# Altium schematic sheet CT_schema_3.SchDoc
size 298 x 247 mm
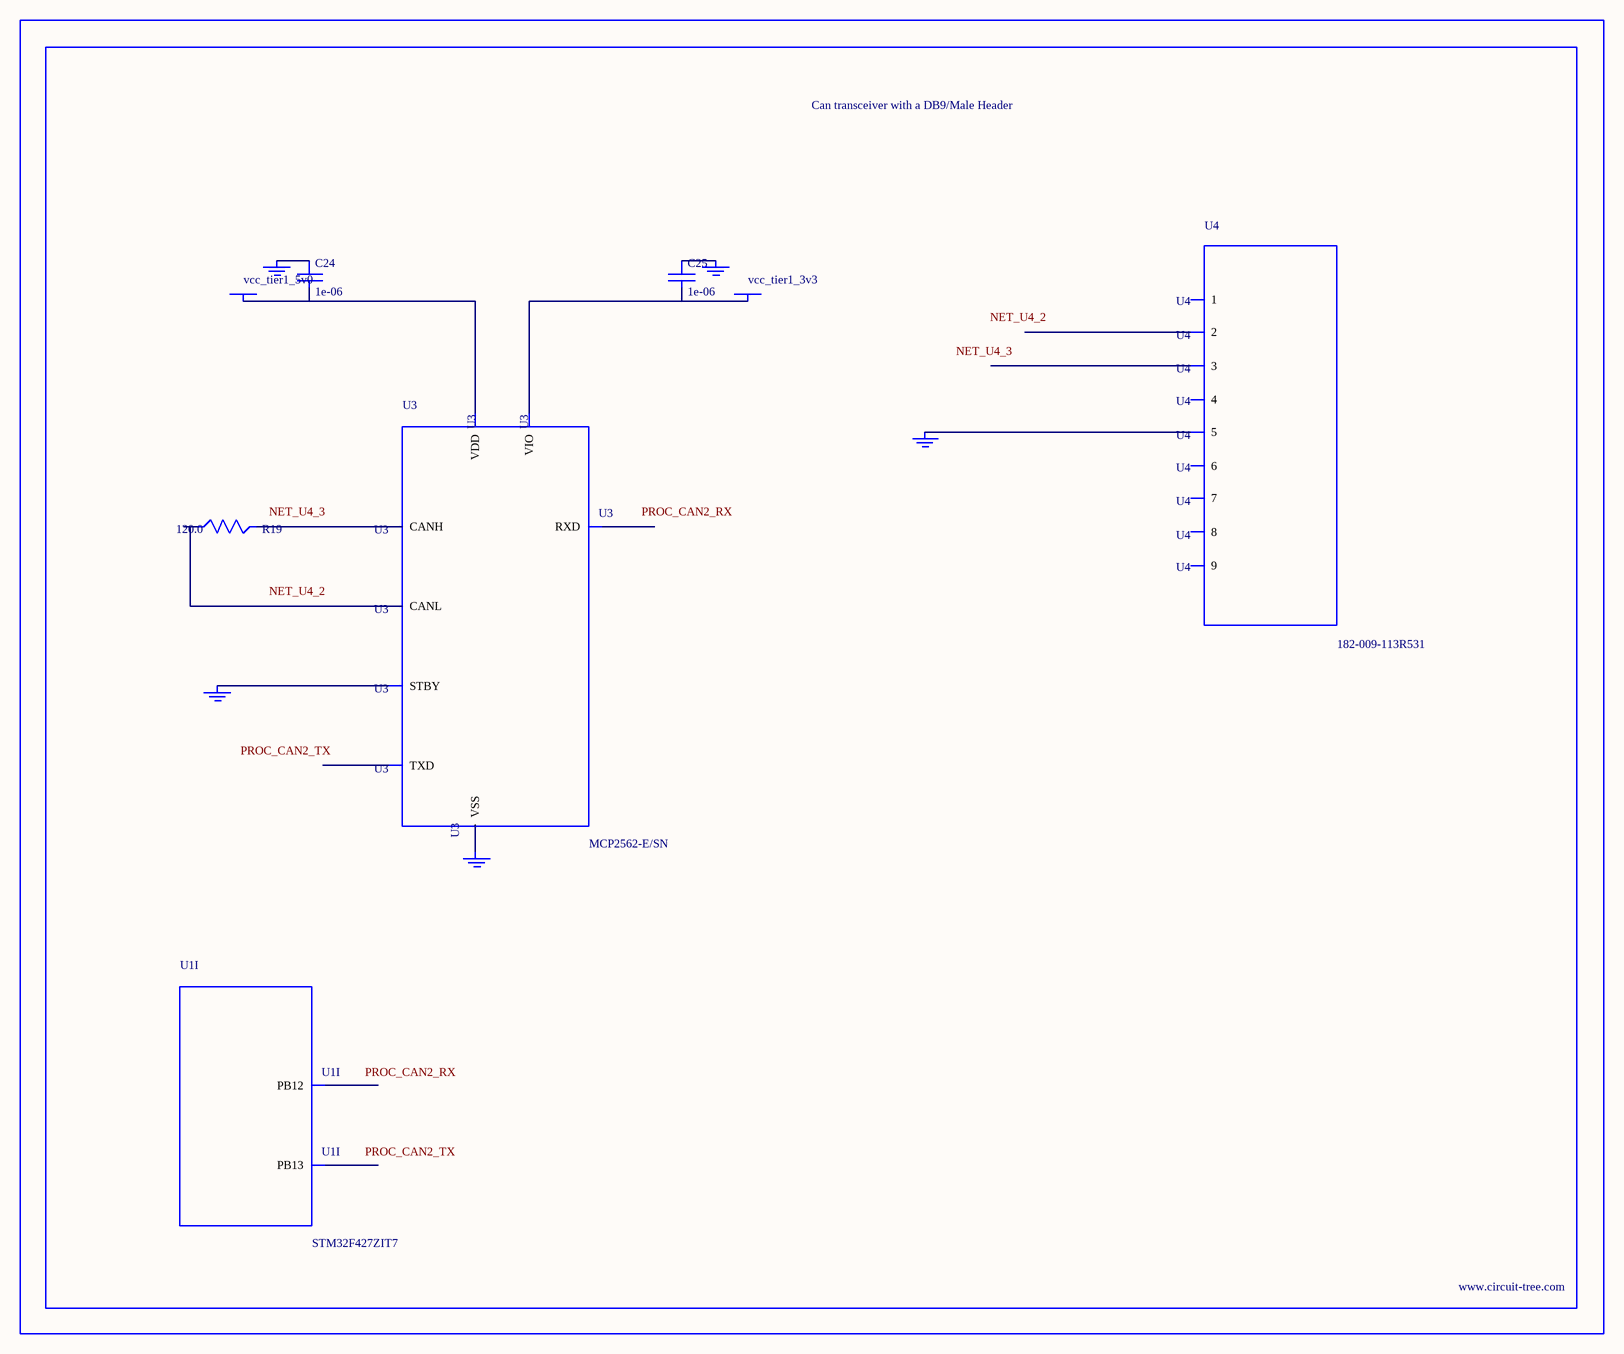
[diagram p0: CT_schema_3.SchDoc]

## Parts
BORDER2  (no value)
C24  1e-06  [C0603]
C25  1e-06  [C0603]
GND_INSTANCE_2_0  (no value)
GND_INSTANCE_2_1  (no value)
GND_INSTANCE_2_2  (no value)
GND_INSTANCE_2_3  (no value)
GND_INSTANCE_2_4  (no value)
POWER_INSTANCE_2_0  vcc_tier1_5v0
POWER_INSTANCE_2_1  vcc_tier1_3v3
R19  120.0  [R0603]
U1  STM32F427ZIT7  [LQFP144]  (part I of 13)
U3  MCP2562-E/SN  [SOIC-8]
U4  182-009-113R531  [182-009-MALE]

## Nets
NetC24_1: C24.1 GND_INSTANCE_2_0.0(GND)
NetC24_2: C24.2 POWER_INSTANCE_2_0.0(PWR) U3.3(VDD)
NetC25_1: C25.1 GND_INSTANCE_2_1.0(GND)
NetC25_2: C25.2 POWER_INSTANCE_2_1.0(PWR) U3.5(VIO)
NetGND_INSTANCE_2_2_0: GND_INSTANCE_2_2.0(GND) U3.8(STBY)
NetGND_INSTANCE_2_3_0: GND_INSTANCE_2_3.0(GND) U3.2(VSS)
NetGND_INSTANCE_2_4_0: GND_INSTANCE_2_4.0(GND) U4.5
NetR19_1: R19.1 U3.6(CANL)
NetR19_2: R19.2 U3.7(CANH)

Not connected (* = marked no-connect by the designer): U1 73(PB12) 74(PB13); U3 1(TXD) 4(RXD); U4 1 2 3 4 6 7 8 9

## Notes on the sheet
- Labels drawn without touching a wire or pin: NET_U4_2, NET_U4_3, PROC_CAN2_RX, PROC_CAN2_TX

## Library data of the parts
BORDER2 = BORDER_PAGE2
C24 C25 = C0603C105K3RACTU
GND_INSTANCE_2_0-GND_INSTANCE_2_4 = GND
POWER_INSTANCE_2_0 POWER_INSTANCE_2_1 = PWR
R19 = RC0603JR-07120RL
